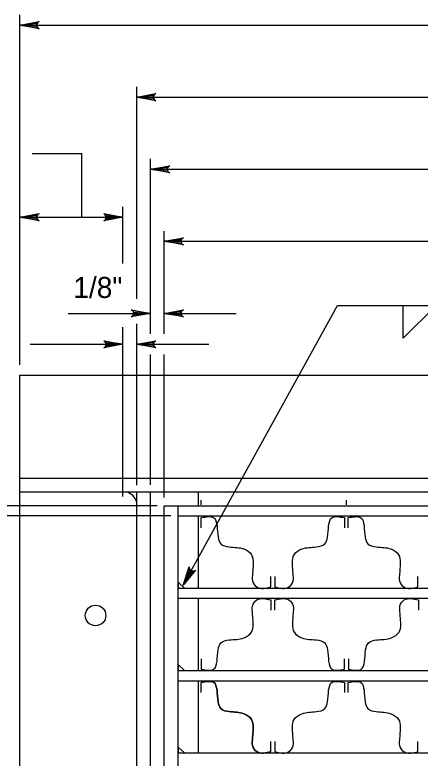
# Model space of a CAD drawing. Extents: x 0.71 to 8.05, y -5.67 to 4.31.
# Drawn here: x 2.185 to 3.343, y 2.109 to 4.233 of the extents above; entities that cross this region are included whole.
import ezdxf

# ---------------------------------------------------------------- set-up
doc = ezdxf.new("R2010")
doc.units = 0
for name, color, linetype in [('DETL-DIMS', 7, 'Continuous'), ('DETL-LINE', 7, 'Continuous'), ('DETL-NOTE', 7, 'Continuous')]:
    doc.layers.add(name, color=color, linetype=linetype)

msp = doc.modelspace()

# ---------------------------------------------------------------- linework, layer by layer
at = {"layer": 'DETL-DIMS'}
for p, q in [((2.1992, 3.233), (2.1992, 4.233)), ((2.1992, 4.2036), (7.0228, 4.2036)), ((2.5328, 3.4218), (2.5328, 4.0271)), ((2.5328, 3.9977), (6.6892, 3.9977)), ((2.2344, 3.8374), (2.3763, 3.8374)), ((2.3763, 3.6548), (2.3763, 3.8374)), ((2.5722, 3.3213), (2.5722, 3.8213)), ((2.5722, 3.7918), (6.6498, 3.7918)), ((2.4933, 3.5228), (2.4933, 3.6842)), ((2.1992, 3.6548), (2.4933, 3.6548)), ((2.6116, 3.3213), (2.6116, 3.6154)), ((2.6116, 3.586), (6.6104, 3.586)), ((2.6651, 2.6032), (3.1063, 3.403)), ((2.3369, 3.3801), (2.5722, 3.3801)), ((2.6116, 3.3801), (2.8175, 3.3801)), ((2.4933, 2.8566), (2.4933, 3.3409)), ((2.5328, 2.8891), (2.5328, 3.3507)), ((2.2286, 3.2918), (2.4933, 3.2918)), ((2.5328, 3.2918), (2.7386, 3.2918)), ((2.5722, 2.8902), (2.5722, 3.2624)), ((2.6116, 2.8544), (2.6116, 3.2624)), ((2.5913, 2.8307), (1.7286, 2.8307)), ((2.6302, 2.8013), (1.9345, 2.8013))]:
    msp.add_line(p, q, dxfattribs=at)
for points in [[(2.1992, 4.2036), (2.2541, 4.2139), (2.2498, 4.211), (2.2477, 4.2073), (2.247, 4.2036), (2.2477, 4.1999), (2.2498, 4.1963), (2.2541, 4.1933), (2.1992, 4.2036), (2.2498, 4.1963), (2.2477, 4.1999), (2.1992, 4.2036), (2.247, 4.2036), (2.2477, 4.2073), (2.1992, 4.2036), (2.2498, 4.211)], [(2.5328, 3.9977), (2.5876, 4.008), (2.5834, 4.0051), (2.5812, 4.0014), (2.5806, 3.9977), (2.5812, 3.9941), (2.5834, 3.9904), (2.5876, 3.9875), (2.5328, 3.9977), (2.5834, 3.9904), (2.5812, 3.9941), (2.5328, 3.9977), (2.5806, 3.9977), (2.5812, 4.0014), (2.5328, 3.9977), (2.5834, 4.0051)], [(2.5722, 3.7918), (2.627, 3.8021), (2.6228, 3.7992), (2.6206, 3.7955), (2.62, 3.7918), (2.6206, 3.7882), (2.6228, 3.7845), (2.627, 3.7816), (2.5722, 3.7918), (2.6228, 3.7845), (2.6206, 3.7882), (2.5722, 3.7918), (2.62, 3.7918), (2.6206, 3.7955), (2.5722, 3.7918), (2.6228, 3.7992)], [(2.1992, 3.6548), (2.2541, 3.6651), (2.2498, 3.6621), (2.2477, 3.6585), (2.247, 3.6548), (2.2477, 3.6511), (2.2498, 3.6474), (2.2541, 3.6445), (2.1992, 3.6548), (2.2498, 3.6474), (2.2477, 3.6511), (2.1992, 3.6548), (2.247, 3.6548), (2.2477, 3.6585), (2.1992, 3.6548), (2.2498, 3.6621)], [(2.4933, 3.6548), (2.4385, 3.6445), (2.4427, 3.6474), (2.4449, 3.6511), (2.4456, 3.6548), (2.4449, 3.6585), (2.4427, 3.6621), (2.4385, 3.6651), (2.4933, 3.6548), (2.4427, 3.6621), (2.4449, 3.6585), (2.4933, 3.6548), (2.4456, 3.6548), (2.4449, 3.6511), (2.4933, 3.6548), (2.4427, 3.6474)], [(2.6116, 3.586), (2.6664, 3.5962), (2.6622, 3.5933), (2.66, 3.5896), (2.6594, 3.586), (2.66, 3.5823), (2.6622, 3.5786), (2.6664, 3.5757), (2.6116, 3.586), (2.6622, 3.5786), (2.66, 3.5823), (2.6116, 3.586), (2.6594, 3.586), (2.66, 3.5896), (2.6116, 3.586), (2.6622, 3.5933)], [(3.1063, 3.403), (3.3886, 3.403), (3.2945, 3.3089), (3.2945, 3.403), (3.5769, 3.403)], [(2.5722, 3.3801), (2.5173, 3.3698), (2.5216, 3.3727), (2.5237, 3.3764), (2.5244, 3.3801), (2.5237, 3.3838), (2.5216, 3.3874), (2.5173, 3.3904), (2.5722, 3.3801), (2.5216, 3.3874), (2.5237, 3.3838), (2.5722, 3.3801), (2.5244, 3.3801), (2.5237, 3.3764), (2.5722, 3.3801), (2.5216, 3.3727)], [(2.6116, 3.3801), (2.6664, 3.3904), (2.6622, 3.3874), (2.66, 3.3838), (2.6594, 3.3801), (2.66, 3.3764), (2.6622, 3.3727), (2.6664, 3.3698), (2.6116, 3.3801), (2.6622, 3.3727), (2.66, 3.3764), (2.6116, 3.3801), (2.6594, 3.3801), (2.66, 3.3838), (2.6116, 3.3801), (2.6622, 3.3874)], [(2.4933, 3.2918), (2.4385, 3.2816), (2.4427, 3.2845), (2.4449, 3.2882), (2.4456, 3.2918), (2.4449, 3.2955), (2.4427, 3.2992), (2.4385, 3.3021), (2.4933, 3.2918), (2.4427, 3.2992), (2.4449, 3.2955), (2.4933, 3.2918), (2.4456, 3.2918), (2.4449, 3.2882), (2.4933, 3.2918), (2.4427, 3.2845)], [(2.5328, 3.2918), (2.5876, 3.3021), (2.5834, 3.2992), (2.5812, 3.2955), (2.5806, 3.2918), (2.5812, 3.2882), (2.5834, 3.2845), (2.5876, 3.2816), (2.5328, 3.2918), (2.5834, 3.2845), (2.5812, 3.2882), (2.5328, 3.2918), (2.5806, 3.2918), (2.5812, 3.2955), (2.5328, 3.2918), (2.5834, 3.2992)], [(2.6651, 2.6032), (2.6826, 2.6562), (2.6831, 2.6511), (2.6853, 2.6474), (2.6882, 2.6451), (2.6917, 2.6439), (2.696, 2.644), (2.7006, 2.6463), (2.6651, 2.6032), (2.696, 2.644), (2.6917, 2.6439), (2.6651, 2.6032), (2.6882, 2.6451), (2.6853, 2.6474), (2.6651, 2.6032), (2.6831, 2.6511)]]:
    msp.add_lwpolyline(points, dxfattribs=at)
at = {"layer": 'DETL-LINE'}
for p, q in [((2.1992, 3.2036), (7.0228, 3.2036)), ((2.1992, 1.3586), (2.1992, 3.2036)), ((2.1992, 2.9095), (7.0228, 2.9095)), ((2.1992, 2.8701), (7.0228, 2.8701)), ((2.5328, 0.8795), (2.5328, 2.8701)), ((2.5722, 0.8795), (2.5722, 2.8701)), ((2.7098, 2.8307), (2.7098, 2.8701)), ((2.7172, 2.8331), (2.7172, 2.8468)), ((3.1321, 2.8331), (3.1321, 2.8468)), ((2.6116, 2.8307), (6.6104, 2.8307)), ((2.6116, 0.9189), (2.6116, 2.8307)), ((2.651, 0.9189), (2.651, 2.8307)), ((2.651, 2.8013), (6.571, 2.8013)), ((2.7098, 2.5954), (2.7098, 2.8013)), ((2.7166, 2.7671), (2.7166, 2.7965)), ((3.127, 2.7965), (3.127, 2.7671)), ((3.1369, 2.7671), (3.1369, 2.7965)), ((2.9162, 2.5984), (2.9162, 2.6279)), ((2.9274, 2.6279), (2.9274, 2.5984)), ((3.3365, 2.5984), (3.3365, 2.6279)), ((2.651, 2.5954), (6.571, 2.5954)), ((2.651, 2.566), (6.571, 2.566)), ((2.7098, 2.3601), (2.7098, 2.566)), ((2.9162, 2.5615), (2.9162, 2.5321)), ((2.9274, 2.5321), (2.9274, 2.5615)), ((3.338, 2.5615), (3.338, 2.5321)), ((2.7166, 2.3929), (2.7166, 2.3634)), ((3.127, 2.3634), (3.127, 2.3929)), ((3.1384, 2.3929), (3.1384, 2.3634)), ((2.651, 2.3601), (6.571, 2.3601)), ((2.651, 2.3307), (6.571, 2.3307)), ((2.7098, 2.1248), (2.7098, 2.3307)), ((2.7166, 2.2965), (2.7166, 2.3259)), ((3.127, 2.3259), (3.127, 2.2965)), ((3.1369, 2.2965), (3.1369, 2.3259)), ((2.9162, 2.1279), (2.9162, 2.1573)), ((2.9274, 2.1573), (2.9274, 2.1279)), ((3.3365, 2.1279), (3.3365, 2.1573)), ((2.651, 2.1248), (6.571, 2.1248))]:
    msp.add_line(p, q, dxfattribs=at)
for points in [[(2.6695, 2.5954), (2.651, 2.6118), (2.651, 2.5954)], [(2.6695, 2.3601), (2.651, 2.3765), (2.651, 2.3601)], [(2.6695, 2.1248), (2.651, 2.1412), (2.651, 2.1248)]]:
    msp.add_lwpolyline(points, close=True, dxfattribs=at)
msp.add_circle((2.4151, 2.517), 0.0294, dxfattribs=at)
msp.add_arc((2.4933, 2.8306), 0.0407, 14.2782, 75.7218, dxfattribs=at)
for points in [[(2.7166, 2.7965), (2.7526, 2.7965), (2.7652, 2.7409), (2.7733, 2.7216), (2.7971, 2.7129), (2.8389, 2.707), (2.8608, 2.6903), (2.8643, 2.6449), (2.8639, 2.6372), (2.8634, 2.6158), (2.8758, 2.5985), (2.9162, 2.5984)], [(2.9274, 2.5984), (2.9678, 2.5985), (2.9801, 2.6158), (2.9797, 2.6372), (2.9792, 2.6449), (2.9828, 2.6903), (3.0047, 2.707), (3.0465, 2.7129), (3.0703, 2.7216), (3.0784, 2.7409), (3.091, 2.7965), (3.127, 2.7965)], [(3.1369, 2.7965), (3.1728, 2.7965), (3.1855, 2.7409), (3.1936, 2.7216), (3.2174, 2.7129), (3.2592, 2.707), (3.2811, 2.6903), (3.2846, 2.6449), (3.2842, 2.6372), (3.2837, 2.6158), (3.2961, 2.5985), (3.3365, 2.5984)], [(2.7166, 2.3634), (2.7526, 2.3634), (2.7652, 2.4191), (2.7733, 2.4384), (2.7971, 2.4471), (2.8389, 2.4529), (2.8608, 2.4696), (2.8643, 2.515), (2.8639, 2.5227), (2.8634, 2.5442), (2.8758, 2.5615), (2.9162, 2.5615)], [(2.9274, 2.5615), (2.9678, 2.5615), (2.9801, 2.5442), (2.9797, 2.5227), (2.9792, 2.515), (2.9828, 2.4696), (3.0047, 2.4529), (3.0465, 2.4471), (3.0703, 2.4384), (3.0784, 2.4191), (3.091, 2.3634), (3.127, 2.3634)], [(3.1384, 2.3634), (3.1744, 2.3634), (3.187, 2.4191), (3.1951, 2.4384), (3.2189, 2.4471), (3.2607, 2.4529), (3.2826, 2.4696), (3.2861, 2.515), (3.2857, 2.5227), (3.2852, 2.5442), (3.2976, 2.5615), (3.338, 2.5615)], [(2.7166, 2.3259), (2.7526, 2.326), (2.7652, 2.2703), (2.7733, 2.251), (2.7971, 2.2423), (2.8389, 2.2364), (2.8608, 2.2198), (2.8643, 2.1743), (2.8639, 2.1666), (2.8634, 2.1452), (2.8758, 2.1279), (2.9162, 2.1279)], [(2.7166, 2.3259), (2.7526, 2.326), (2.7652, 2.2703), (2.7733, 2.251), (2.7971, 2.2423), (2.8389, 2.2364), (2.8608, 2.2198), (2.8643, 2.1743), (2.8639, 2.1666), (2.8634, 2.1452), (2.8758, 2.1279), (2.9162, 2.1279)], [(2.9162, 2.1279), (2.8758, 2.1279), (2.8634, 2.1452), (2.8639, 2.1666), (2.8643, 2.1743), (2.8608, 2.2198), (2.8389, 2.2364), (2.7971, 2.2423), (2.7733, 2.251), (2.7652, 2.2703), (2.7526, 2.326), (2.7166, 2.3259)], [(2.7166, 2.3259), (2.7526, 2.326), (2.7652, 2.2703), (2.7733, 2.251), (2.7971, 2.2423), (2.8389, 2.2364), (2.8608, 2.2198), (2.8643, 2.1743), (2.8639, 2.1666), (2.8634, 2.1452), (2.8758, 2.1279), (2.9162, 2.1279)], [(2.7166, 2.3259), (2.7526, 2.326), (2.7652, 2.2703), (2.7733, 2.251), (2.7971, 2.2423), (2.8389, 2.2364), (2.8608, 2.2198), (2.8643, 2.1743), (2.8639, 2.1666), (2.8634, 2.1452), (2.8758, 2.1279), (2.9162, 2.1279)], [(2.9274, 2.1279), (2.9678, 2.1279), (2.9801, 2.1452), (2.9797, 2.1666), (2.9792, 2.1743), (2.9828, 2.2198), (3.0047, 2.2364), (3.0465, 2.2423), (3.0703, 2.251), (3.0784, 2.2703), (3.091, 2.326), (3.127, 2.3259)], [(2.9274, 2.1279), (2.9678, 2.1279), (2.9801, 2.1452), (2.9797, 2.1666), (2.9792, 2.1743), (2.9828, 2.2198), (3.0047, 2.2364), (3.0465, 2.2423), (3.0703, 2.251), (3.0784, 2.2703), (3.091, 2.326), (3.127, 2.3259)], [(2.9274, 2.1279), (2.9678, 2.1279), (2.9801, 2.1452), (2.9797, 2.1666), (2.9792, 2.1743), (2.9828, 2.2198), (3.0047, 2.2364), (3.0465, 2.2423), (3.0703, 2.251), (3.0784, 2.2703), (3.091, 2.326), (3.127, 2.3259)], [(3.1369, 2.3259), (3.1728, 2.326), (3.1855, 2.2703), (3.1936, 2.251), (3.2174, 2.2423), (3.2592, 2.2364), (3.2811, 2.2198), (3.2846, 2.1743), (3.2842, 2.1666), (3.2837, 2.1452), (3.2961, 2.1279), (3.3365, 2.1279)], [(3.1369, 2.3259), (3.1728, 2.326), (3.1855, 2.2703), (3.1936, 2.251), (3.2174, 2.2423), (3.2592, 2.2364), (3.2811, 2.2198), (3.2846, 2.1743), (3.2842, 2.1666), (3.2837, 2.1452), (3.2961, 2.1279), (3.3365, 2.1279)], [(3.1369, 2.3259), (3.1728, 2.326), (3.1855, 2.2703), (3.1936, 2.251), (3.2174, 2.2423), (3.2592, 2.2364), (3.2811, 2.2198), (3.2846, 2.1743), (3.2842, 2.1666), (3.2837, 2.1452), (3.2961, 2.1279), (3.3365, 2.1279)]]:
    msp.add_spline(points, degree=3, dxfattribs=at)

# ---------------------------------------------------------------- texts
at = {"layer": 'DETL-NOTE'}
msp.add_text('1/8"', height=0.06, dxfattribs=at).set_placement((2.3517, 3.4242))

doc.saveas('drawing.dxf')
